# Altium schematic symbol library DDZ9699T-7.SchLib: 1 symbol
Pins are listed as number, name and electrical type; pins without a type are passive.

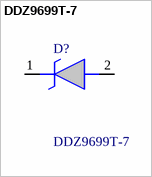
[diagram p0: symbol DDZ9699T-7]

## DDZ9699T-7
designator D?
Diodes Inc DDZ9699T-7 Zener Diode, 12V 5% 150 mW SMT 2-Pin SOD-523; Manufacturer_Name: Diodes Incorporated; Geometry.Height: 0.65mm
footprint SODFL1608X65N
pins: 1 K, 2 A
